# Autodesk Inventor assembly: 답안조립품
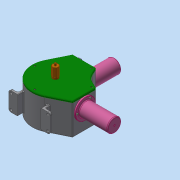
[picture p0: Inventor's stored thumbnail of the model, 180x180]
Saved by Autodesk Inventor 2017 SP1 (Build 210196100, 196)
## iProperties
Part Number: 답안조립품
Material: 일반
Document SubType Name: Assembly
Designer: MRC
Author: MRC
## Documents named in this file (13)
- C:\Users\MRC\Desktop\611109V1010\답안조립품.iam
- C:\Users\MRC\Desktop\611109V1010\본체.ipt
- C:\Users\MRC\Desktop\611109V1010\너트 M3.ipt
- C:\Users\MRC\Desktop\611109V1010\베어링 20 x 37 x 9.ipt
- C:\Users\MRC\Desktop\611109V1010\볼트 M3 x 12.ipt
- C:\Users\MRC\Desktop\611109V1010\실린더.ipt
- C:\Users\MRC\Desktop\611109V1010\앞커버.ipt
- C:\Users\MRC\Desktop\611109V1010\축.ipt
- C:\Users\MRC\Desktop\611109V1010\측정게이지.ipt
- C:\Users\MRC\Desktop\611109V1010\커넥팅로드 캡.ipt
- C:\Users\MRC\Desktop\611109V1010\커넥팅로드.ipt
- C:\Users\MRC\Desktop\611109V1010\피스톤 핀.ipt
- C:\Users\MRC\Desktop\611109V1010\피스톤.ipt
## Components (4 placed, 2 different names)
1. 피스톤 핀:1
2. 피스톤:1
3. 피스톤:2
4. 피스톤 핀:2
